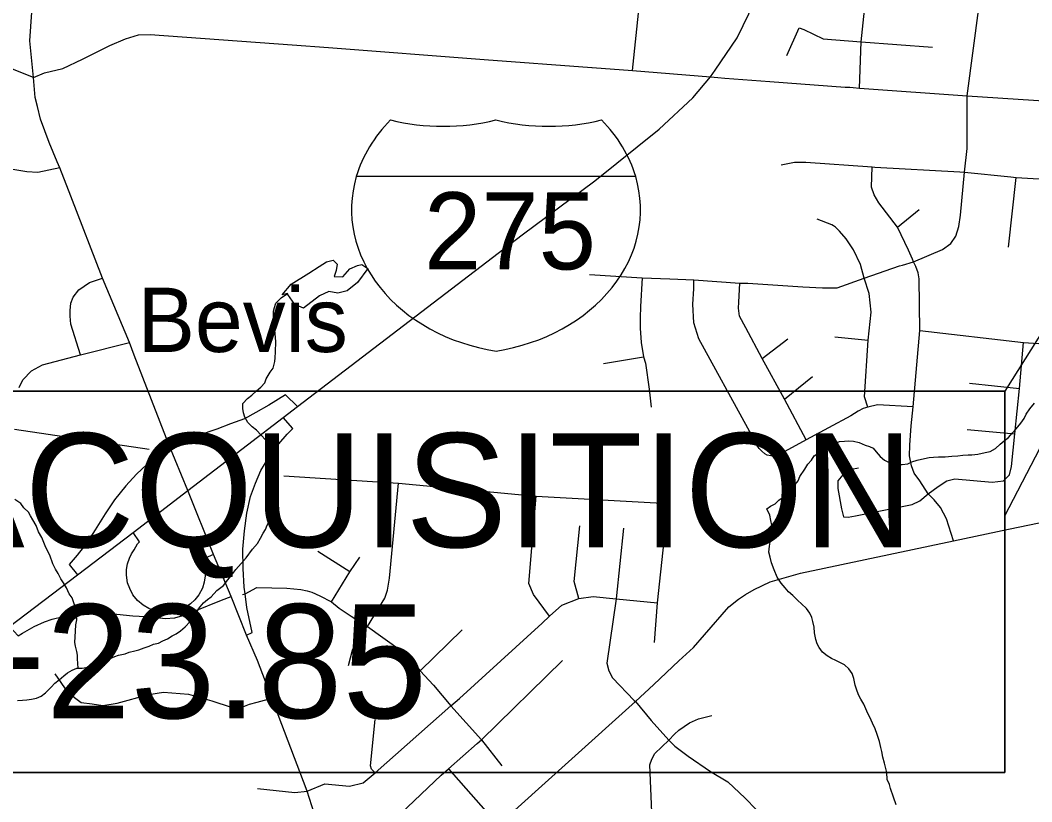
# Model space of a CAD drawing. Extents: x 0 to 34, y 0 to 22.
# Drawn here: x 3.515 to 4.758, y 17.598 to 18.558 of the extents above; entities that cross this region are included whole.
import ezdxf

# ---------------------------------------------------------------- set-up
doc = ezdxf.new("R2010")
doc.units = 0
for name, color, linetype in [('GM_X_County_Road', 7, 'Continuous'), ('GM_X_Interchange_Ramps', 7, 'Continuous'), ('GM_X_Interstate_Location', 7, 'Continuous'), ('GM_X_Interstate_Route', 7, 'Continuous'), ('GM_X_Interstate_Shield', 7, 'Continuous'), ('GM_X_Minor_Lake', 7, 'Continuous'), ('GM_X_Minor_River', 7, 'Continuous'), ('GM_X_Township_Subdivision', 7, 'Continuous'), ('GM_X_Unincorporated_Text', 7, 'Continuous'), ('GM_X_US_Route', 7, 'Continuous'), ('RD_P_Text', 7, 'Continuous'), ('SH_Masking', 7, 'Continuous')]:
    doc.layers.add(name, color=color, linetype=linetype)

msp = doc.modelspace()

# ---------------------------------------------------------------- linework, layer by layer
at = {"layer": 'GM_X_County_Road'}
for points in [[(4.6785, 18.4652), (4.6932, 18.5761), (4.7051, 18.709), (4.7086, 18.7436), (4.7231, 18.9689)], [(4.2674, 18.4962), (4.2756, 18.5744)], [(3.5314, 18.4877), (3.5056, 18.4981), (3.4834, 18.5132), (3.4753, 18.5266), (3.4615, 18.5439), (3.4483, 18.5622)], [(3.5314, 18.4877), (3.5447, 18.4933), (3.5672, 18.4989), (3.5917, 18.5101), (3.6253, 18.5269), (3.6442, 18.5353), (3.6603, 18.5402), (3.6746, 18.5404), (3.8492, 18.5279), (3.8937, 18.5247), (4.085, 18.5097), (4.2173, 18.4999), (4.2176, 18.4999)], [(4.2176, 18.4999), (4.2674, 18.4962), (4.3632, 18.4884), (4.3722, 18.4877), (4.3808, 18.4871)], [(4.3808, 18.4871), (4.4361, 18.483), (4.5287, 18.4761), (4.5341, 18.4757), (4.5384, 18.4754)], [(4.5384, 18.4754), (4.5461, 18.4748), (4.6785, 18.4652), (4.9418, 18.4482), (5.15, 18.4371), (5.2136, 18.4338), (5.4078, 18.4238), (5.4377, 18.4223), (5.5969, 18.4142)], [(3.5889, 18.1471), (3.5773, 18.1847), (3.5762, 18.1946), (3.5765, 18.2018), (3.5773, 18.2108), (3.5799, 18.218), (3.5872, 18.2272), (3.6002, 18.2359), (3.6162, 18.2412)], [(3.5137, 18.1072), (3.5183, 18.1165), (3.529, 18.1275), (3.5423, 18.135), (3.5889, 18.1471), (3.6491, 18.1624)], [(3.5081, 18.0561), (3.6734, 18.0314)], [(3.9249, 17.4139), (4.1024, 17.5697), (4.2708, 17.7213), (4.2935, 17.7424), (4.3241, 17.7714), (4.3423, 17.7879), (4.3557, 17.8032), (4.3855, 17.8377), (4.3976, 17.8473), (4.4059, 17.853), (4.4167, 17.859), (4.4366, 17.8686), (4.4737, 17.8792), (4.6617, 17.9188), (4.7291, 17.933), (4.8264, 17.9531), (4.956, 17.9799), (5.1816, 18.0264), (5.2178, 18.0345), (5.2322, 18.0349), (5.2647, 18.0331), (5.4907, 18.0227), (5.5592, 18.0196)]]:
    msp.add_lwpolyline(points, dxfattribs=at)
at = {"layer": 'GM_X_Interchange_Ramps'}
for points in [[(3.8558, 18.0839), (3.8408, 18.0981), (3.8205, 18.0852), (3.8043, 18.0764), (3.7905, 18.0687), (3.7732, 18.0624), (3.7567, 18.0561), (3.7336, 18.0483), (3.7062, 18.0404), (3.6977, 18.0372)], [(3.7932, 17.8031), (3.8002, 17.8062), (3.7935, 17.8369), (3.7914, 17.8536), (3.7903, 17.8618), (3.7888, 17.8849), (3.7887, 17.9084), (3.7906, 17.931), (3.7933, 17.9528), (3.7981, 17.9733), (3.8041, 17.9898), (3.8108, 18.005), (3.8195, 18.0197), (3.8329, 18.0379), (3.8428, 18.0499), (3.8499, 18.0567), (3.8382, 18.0704)], [(3.6977, 18.0372), (3.6886, 18.0297), (3.682, 18.0233), (3.6705, 18.0125), (3.658, 18.0007), (3.6447, 17.9865), (3.631, 17.9691), (3.6193, 17.9519), (3.6071, 17.9324), (3.5967, 17.9163), (3.5852, 17.9011), (3.5753, 17.8898), (3.5855, 17.8769)], [(3.7523, 17.9019), (3.7421, 17.8975), (3.743, 17.8895), (3.7423, 17.8759), (3.7411, 17.868), (3.7388, 17.8607), (3.7346, 17.8526), (3.7297, 17.8464), (3.7244, 17.8414), (3.7177, 17.8369), (3.7104, 17.8336), (3.7023, 17.8314), (3.6952, 17.8307), (3.6874, 17.8312), (3.68, 17.8328), (3.6729, 17.8356), (3.6659, 17.8397), (3.6591, 17.8456), (3.6535, 17.8526), (3.6495, 17.8601), (3.647, 17.8674), (3.6457, 17.8765), (3.6458, 17.8837), (3.647, 17.8906), (3.6492, 17.8974), (3.6518, 17.9028), (3.6551, 17.9079), (3.6592, 17.9152), (3.6614, 17.9174), (3.6539, 17.9292)], [(3.5019, 17.8134), (3.5125, 17.8021), (3.5177, 17.8053), (3.5323, 17.8134), (3.5449, 17.8194), (3.5543, 17.8225), (3.5679, 17.8259), (3.5818, 17.8276), (3.5997, 17.8288), (3.626, 17.8297), (3.6535, 17.8268), (3.6765, 17.8253), (3.6933, 17.8234), (3.705, 17.8243), (3.7177, 17.8281), (3.7299, 17.8329), (3.7623, 17.8458), (3.7741, 17.8506)]]:
    msp.add_lwpolyline(points, dxfattribs=at)
at = {"layer": 'GM_X_Interstate_Route'}
for points in [[(4.3688, 18.4966), (4.396, 18.5364), (4.4605, 18.6699), (4.5302, 18.8182), (4.5651, 18.8806), (4.6006, 18.9309), (4.6486, 18.9891), (4.7052, 19.0496), (4.7706, 19.1075), (4.9553, 19.2548), (5.2358, 19.4841)], [(3.7943, 18.0368), (3.8382, 18.0704), (3.8558, 18.0839), (4.1317, 18.2944), (4.2208, 18.3608), (4.3, 18.4242), (4.3415, 18.4627), (4.3632, 18.4884), (4.3688, 18.4966)], [(3.721, 17.9807), (3.7943, 18.0368)], [(2.181, 16.4629), (2.2273, 16.5312), (2.2674, 16.589), (2.34, 16.6943), (2.3633, 16.7237), (2.4215, 16.7861), (2.4393, 16.8007), (2.4586, 16.8179), (2.4894, 16.8393), (2.7155, 16.9908), (2.8497, 17.0804), (2.9292, 17.1425), (3.0025, 17.2108), (3.0522, 17.2646), (3.1203, 17.3605), (3.2374, 17.5377), (3.2788, 17.5999), (3.3097, 17.642), (3.3406, 17.6772), (3.3886, 17.7251), (3.5019, 17.8134), (3.5855, 17.8769), (3.6539, 17.9292), (3.721, 17.9807)]]:
    msp.add_lwpolyline(points, dxfattribs=at)
at = {"layer": 'GM_X_Interstate_Shield'}
msp.add_line((4.2713, 18.3661), (3.9279, 18.3661), dxfattribs=at)
msp.add_line((4.2713, 18.3661), (3.9279, 18.3661), dxfattribs=at)
for centre, start_param, end_param in [((4.144, 18.3255), 2.47259, 2.911027), ((4.0347, 18.6054), 4.415841, 5.008937), ((4.1644, 18.6054), 4.415841, 5.008937), ((4.0552, 18.3255), 0.230566, 0.669003), ((4.144, 18.3255), 2.911027, 4.511031), ((4.0552, 18.3255), 4.913747, 6.513751)]:
    msp.add_ellipse(centre, major_axis=(0.2219, 0), ratio=0.8, start_param=start_param, end_param=end_param, dxfattribs=at)
at = {"layer": 'GM_X_Minor_Lake'}
for points in [[(3.8434, 18.2226), (3.837, 18.2207), (3.8479, 18.2338), (3.8695, 18.2475), (3.8822, 18.2556), (3.8914, 18.2615), (3.8994, 18.2636), (3.9046, 18.2585), (3.903, 18.2506), (3.9009, 18.2434), (3.9115, 18.2428), (3.9201, 18.2529), (3.9293, 18.2569), (3.9346, 18.2583), (3.9421, 18.2532), (3.9296, 18.236), (3.9169, 18.2256), (3.9051, 18.2231), (3.8941, 18.2249), (3.8826, 18.2198)], [(3.8826, 18.2198), (3.8629, 18.2046), (3.8523, 18.209), (3.8439, 18.2213), (3.8434, 18.2226)]]:
    msp.add_lwpolyline(points, dxfattribs=at)
at = {"layer": 'GM_X_Minor_River'}
for points in [[(3.8271, 17.9985), (3.8268, 18.0035), (3.827, 18.0092), (3.8282, 18.0149), (3.8283, 18.0206), (3.8273, 18.0255), (3.8255, 18.0313), (3.8215, 18.0375), (3.8163, 18.0429), (3.8111, 18.0487), (3.8055, 18.0549), (3.7999, 18.0588), (3.7947, 18.0642), (3.791, 18.0708), (3.7892, 18.0758), (3.7886, 18.0811), (3.7887, 18.0876), (3.7941, 18.0935), (3.7995, 18.0976), (3.8053, 18.1028), (3.8107, 18.1077), (3.8154, 18.1129), (3.817, 18.1178), (3.8221, 18.1261), (3.8256, 18.1309), (3.8277, 18.1389), (3.8282, 18.1434), (3.8287, 18.1507), (3.8289, 18.1632), (3.8287, 18.1685), (3.8284, 18.1731), (3.8277, 18.1781), (3.8271, 18.1834), (3.8264, 18.188), (3.8262, 18.1941), (3.8263, 18.2009), (3.8275, 18.2054), (3.8292, 18.2107), (3.8357, 18.2171), (3.8434, 18.2226)], [(4.5586, 18.0345), (4.5631, 18.0325), (4.5668, 18.0279), (4.5716, 18.0224), (4.5768, 18.0178), (4.5843, 18.0142), (4.5904, 18.0126), (4.5984, 18.0124), (4.6056, 18.0134), (4.6106, 18.016), (4.6171, 18.0177), (4.6262, 18.0198), (4.6316, 18.0212), (4.6369, 18.0215), (4.6433, 18.0218), (4.6513, 18.022), (4.6597, 18.0226), (4.6669, 18.0232), (4.673, 18.0238), (4.6795, 18.0245), (4.684, 18.0244), (4.6916, 18.0254), (4.7004, 18.0271), (4.7065, 18.0285), (4.7134, 18.0322), (4.7188, 18.0374), (4.7238, 18.0418), (4.7292, 18.0455), (4.7339, 18.0511), (4.7386, 18.0564), (4.7444, 18.0631), (4.7483, 18.0691), (4.7511, 18.0744), (4.7554, 18.0808), (4.7612, 18.0879)], [(4.5914, 17.5945), (4.5878, 17.6041), (4.5842, 17.6148), (4.5832, 17.6194), (4.5803, 17.6259), (4.5797, 17.6343), (4.5783, 17.6393), (4.5769, 17.6458), (4.5747, 17.6531), (4.5734, 17.6603), (4.5723, 17.6649), (4.5706, 17.6725), (4.5677, 17.681), (4.5652, 17.6879), (4.5623, 17.6948), (4.5587, 17.7021), (4.5565, 17.7067), (4.5514, 17.7182), (4.5477, 17.7243), (4.5455, 17.729), (4.5434, 17.7343), (4.5409, 17.7416), (4.5391, 17.7496), (4.537, 17.7557), (4.5329, 17.7615), (4.5277, 17.7666), (4.5228, 17.769), (4.5172, 17.7717), (4.5119, 17.7745), (4.5063, 17.7777), (4.5007, 17.782), (4.4966, 17.7877), (4.4941, 17.7924), (4.4923, 17.7977), (4.4909, 17.8057), (4.4903, 17.8126), (4.4889, 17.8198), (4.4875, 17.8248), (4.4853, 17.8298), (4.4809, 17.8356), (4.4749, 17.8414), (4.4705, 17.8457), (4.4641, 17.8515), (4.4589, 17.8562), (4.4548, 17.8612), (4.45, 17.867), (4.4452, 17.874), (4.4412, 17.8832), (4.438, 17.8916), (4.4362, 17.8989), (4.4348, 17.905), (4.4354, 17.9122), (4.4362, 17.9171), (4.4375, 17.9232), (4.4384, 17.9296), (4.4386, 17.938), (4.4372, 17.9437), (4.4361, 17.9502), (4.4321, 17.9579), (4.4368, 17.9612), (4.4425, 17.9642), (4.4471, 17.9686), (4.4525, 17.9723), (4.4572, 17.9768), (4.4634, 17.9831), (4.4673, 17.988), (4.4708, 17.9925), (4.4728, 17.9978), (4.4791, 18.0068), (4.4826, 18.0128), (4.4872, 18.0177), (4.4904, 18.0233), (4.4988, 18.0285), (4.5042, 18.0325), (4.5104, 18.0366), (4.5158, 18.0384), (4.5215, 18.0406), (4.5276, 18.0412), (4.5329, 18.0415), (4.5386, 18.041), (4.5458, 18.0397), (4.5533, 18.0361), (4.5586, 18.0345)], [(3.5118, 17.7226), (3.5179, 17.7233), (3.5232, 17.7236), (3.5289, 17.7242), (3.535, 17.7256), (3.5407, 17.7281), (3.5461, 17.7322), (3.5531, 17.7393), (3.5574, 17.7442), (3.5628, 17.7482), (3.5686, 17.7531), (3.5732, 17.7568), (3.579, 17.7601), (3.5847, 17.7623), (3.5912, 17.7625), (3.5957, 17.7632), (3.6007, 17.7638), (3.606, 17.7656), (3.6121, 17.7682), (3.6175, 17.7707), (3.6256, 17.7744), (3.6313, 17.7769), (3.6359, 17.7784), (3.6439, 17.7801), (3.6489, 17.7819), (3.6557, 17.7837), (3.6607, 17.7851), (3.6672, 17.7876), (3.6733, 17.7894), (3.6787, 17.7919), (3.6848, 17.7933), (3.6901, 17.7959), (3.6959, 17.7984), (3.7017, 17.8021), (3.7067, 17.8047), (3.712, 17.8084), (3.7175, 17.8132), (3.7237, 17.8196), (3.7275, 17.8241), (3.7314, 17.8293), (3.7342, 17.8353), (3.7404, 17.8428), (3.7451, 17.8469), (3.7497, 17.8499), (3.7567, 17.8577), (3.7648, 17.864), (3.7703, 17.8711), (3.7749, 17.8771), (3.78, 17.8835), (3.7866, 17.891), (3.7928, 17.8981), (3.8006, 17.9086), (3.8065, 17.9157), (3.8104, 17.922), (3.8135, 17.9281), (3.8163, 17.9326), (3.8183, 17.9379), (3.8215, 17.9439), (3.8247, 17.956), (3.826, 17.9621), (3.8269, 17.97), (3.827, 17.975), (3.8265, 17.9856), (3.827, 17.9928), (3.8271, 17.9985)], [(3.5861, 17.7623), (3.5853, 17.7737), (3.5854, 17.7782), (3.5844, 17.7828), (3.583, 17.7893), (3.5823, 17.7939), (3.5824, 17.8011), (3.583, 17.8079), (3.5835, 17.8155), (3.5844, 17.8216), (3.5841, 17.8262), (3.5827, 17.833), (3.5821, 17.8388), (3.5803, 17.8437), (3.5789, 17.8487), (3.5752, 17.8537), (3.5719, 17.861), (3.5682, 17.8672), (3.5649, 17.8722), (3.5616, 17.8787), (3.5583, 17.8841), (3.555, 17.8907), (3.5515, 17.9014), (3.5485, 17.9064), (3.5456, 17.9125), (3.5416, 17.9229), (3.5376, 17.9298), (3.5347, 17.9378), (3.5307, 17.9444), (3.5278, 17.9494), (3.5252, 17.954), (3.5196, 17.9594), (3.5159, 17.9648), (3.5084, 17.9696)]]:
    msp.add_lwpolyline(points, dxfattribs=at)
at = {"layer": 'GM_X_Township_Subdivision'}
for points in [[(4.5461, 18.4748), (4.548, 18.5316), (4.5541, 18.5864), (4.5589, 18.6315)], [(4.4568, 18.5147), (4.4722, 18.5486), (4.4776, 18.5468), (4.5015, 18.5352), (4.548, 18.5316), (4.6359, 18.5252)], [(4.5988, 18.2574), (4.6127, 18.2616), (4.648, 18.2766), (4.6584, 18.284), (4.6645, 18.2929), (4.6683, 18.3047), (4.6704, 18.3186), (4.6751, 18.3717), (4.6785, 18.4006), (4.6785, 18.4652)], [(3.5637, 18.377), (3.5367, 18.371), (3.5232, 18.3719), (3.488, 18.3776), (3.3929, 18.3966), (3.1812, 18.4357)], [(4.4501, 18.3805), (4.4662, 18.3837), (4.4804, 18.384), (4.5617, 18.3779), (4.5648, 18.3777)], [(4.6114, 18.2645), (4.6113, 18.2648), (4.6065, 18.2756), (4.593, 18.304), (4.57, 18.3339), (4.5642, 18.3435), (4.5609, 18.3529), (4.5617, 18.3779)], [(4.5648, 18.3777), (4.6693, 18.372)], [(4.6693, 18.372), (4.6751, 18.3717), (4.7319, 18.3656)], [(4.7294, 18.2794), (4.7387, 18.3649)], [(4.7319, 18.3656), (4.7387, 18.3649), (4.7946, 18.3616)], [(4.593, 18.304), (4.6194, 18.3258)], [(4.5565, 18.0831), (4.5521, 18.0957), (4.557, 18.1651), (4.5603, 18.1995), (4.558, 18.2226), (4.5519, 18.2414), (4.5473, 18.258), (4.5387, 18.2762), (4.5296, 18.2897), (4.5215, 18.2991), (4.5167, 18.3039), (4.5141, 18.3057), (4.5123, 18.307), (4.4943, 18.3136)], [(4.2143, 18.2459), (4.279, 18.2419), (4.313, 18.2406), (4.3427, 18.2391), (4.399, 18.2353), (4.409, 18.2351), (4.4766, 18.2308), (4.5007, 18.2296), (4.5187, 18.2293), (4.5519, 18.2414), (4.5953, 18.2563), (4.5988, 18.2574)], [(4.6154, 18.2555), (4.6153, 18.2557), (4.6127, 18.2616), (4.6114, 18.2645)], [(4.6617, 17.9188), (4.6531, 17.9459), (4.6456, 17.9597), (4.6379, 17.9692), (4.6305, 17.9764), (4.6202, 17.9924), (4.6133, 18.0019), (4.6102, 18.0111), (4.6074, 18.0232), (4.6079, 18.0361), (4.6097, 18.0602), (4.612, 18.0833), (4.6202, 18.1771), (4.6195, 18.2407), (4.6182, 18.2479), (4.6154, 18.2555)], [(4.279, 18.2419), (4.2771, 18.2064), (4.2767, 18.1927), (4.2767, 18.1798), (4.2781, 18.1623), (4.2809, 18.1447), (4.2834, 18.137), (4.2877, 18.105), (4.2901, 18.0829)], [(4.612, 18.0833), (4.5683, 18.0859), (4.5565, 18.0831), (4.5508, 18.0813), (4.5444, 18.0782), (4.5354, 18.0723), (4.4808, 18.0427), (4.4498, 18.0262), (4.4422, 18.023), (4.4372, 18.023), (4.4329, 18.0238), (4.4299, 18.0258), (4.426, 18.0288), (4.4228, 18.0321), (4.4193, 18.0377), (4.4091, 18.0571), (4.3489, 18.1668), (4.3426, 18.1865), (4.3412, 18.2093), (4.3427, 18.2281), (4.3427, 18.2391)], [(4.4808, 18.0427), (4.4539, 18.0928), (4.4267, 18.1429), (4.4064, 18.1805), (4.3986, 18.1948), (4.3975, 18.2046), (4.3979, 18.2119), (4.3985, 18.2198), (4.399, 18.2353)], [(4.5159, 18.1692), (4.557, 18.1651)], [(4.6202, 18.1771), (4.7476, 18.1625), (4.7786, 18.1601)], [(4.4267, 18.1429), (4.458, 18.1669)], [(4.5451, 18.008), (4.5363, 18.0062), (4.5278, 18.0024), (4.5194, 17.9926), (4.5196, 17.9832), (4.524, 17.9579), (4.5263, 17.9484), (4.5322, 17.948), (4.5413, 17.9493), (4.611, 17.9636), (4.6202, 17.968), (4.6305, 17.9764), (4.6426, 17.9854), (4.6533, 17.9926), (4.6634, 17.9949), (4.7093, 17.991), (4.723, 17.9926), (4.7304, 17.9998), (4.733, 18.0101), (4.7369, 18.0502), (4.7428, 18.1059), (4.7476, 18.1625)], [(4.2315, 18.1366), (4.2809, 18.1447)], [(4.4539, 18.0928), (4.4884, 18.1204)], [(4.6815, 18.1126), (4.7428, 18.1059)], [(4.6786, 18.0557), (4.7369, 18.0502)], [(3.8388, 17.9987), (3.9796, 17.9895), (4.1489, 17.9738), (4.3036, 17.965)], [(3.9182, 17.7657), (3.9233, 17.7844), (3.929, 17.7976), (3.9338, 17.8055), (3.9418, 17.8134), (3.9629, 17.8485), (3.9661, 17.8583), (3.9689, 17.8731), (3.9796, 17.9895)], [(4.1652, 17.8262), (4.1458, 17.8527), (4.1397, 17.8665), (4.1489, 17.9738)], [(4.2013, 17.8481), (4.1957, 17.8687), (4.2024, 17.9373)], [(4.2562, 17.9342), (4.2473, 17.8474), (4.2359, 17.7686), (4.2383, 17.7593), (4.2427, 17.7504), (4.2693, 17.7229)], [(4.2944, 17.794), (4.2981, 17.8425), (4.3061, 17.9189)], [(3.9199, 17.8809), (3.8807, 17.9059)], [(3.8975, 17.8437), (3.9199, 17.8809), (3.9321, 17.8986)], [(3.7881, 17.8528), (3.7914, 17.8536), (3.8059, 17.8614), (3.8426, 17.8605), (3.8598, 17.8592), (3.8675, 17.8576), (3.8734, 17.8559), (3.8833, 17.8512), (3.8975, 17.8437), (3.9067, 17.8362), (3.9215, 17.8264), (3.9418, 17.8134), (3.9822, 17.7847), (3.9936, 17.7749), (4.0066, 17.7593), (4.0226, 17.7417), (4.0442, 17.7161), (4.0818, 17.6746), (4.1066, 17.6426)], [(4.1561, 17.8178), (4.1652, 17.8262), (4.1804, 17.8396), (4.2013, 17.8481), (4.219, 17.8503), (4.2473, 17.8474), (4.2981, 17.8425)], [(3.8675, 17.6115), (3.8893, 17.6206), (3.9197, 17.6174), (3.9365, 17.6215), (3.951, 17.634), (4.0442, 17.7161), (4.0549, 17.7251), (4.1561, 17.8178)], [(4.0066, 17.7593), (4.0582, 17.8097)], [(4.0763, 17.6698), (4.0818, 17.6746), (4.1814, 17.7718)], [(3.5575, 17.7553), (3.5731, 17.7328), (3.5901, 17.7203), (3.6036, 17.7187), (3.6165, 17.7166), (3.634, 17.7193), (3.6729, 17.7299), (3.6911, 17.733), (3.7216, 17.7304), (3.7504, 17.7224), (3.774, 17.7145), (3.7846, 17.714), (3.7904, 17.7156), (3.7967, 17.7182), (3.8063, 17.7206), (3.8241, 17.7258)], [(4.2693, 17.7229), (4.2708, 17.7213), (4.2901, 17.6981), (4.3117, 17.6741), (4.3192, 17.6665), (4.3355, 17.6543), (4.363, 17.6356), (4.3842, 17.6228), (4.4055, 17.6026), (4.4193, 17.5888), (4.4209, 17.587)], [(3.951, 17.634), (3.9465, 17.6384), (3.9454, 17.6423), (3.9511, 17.6993)], [(4.319, 17.6813), (4.3243, 17.6865), (4.3374, 17.6955), (4.3484, 17.7003), (4.3646, 17.7043)], [(4.2976, 17.5167), (4.2953, 17.539), (4.2912, 17.5856), (4.2885, 17.6437), (4.2909, 17.6505), (4.2949, 17.6578), (4.3117, 17.6741), (4.319, 17.6813)], [(4.0324, 17.631), (4.0411, 17.6387), (4.0763, 17.6698)], [(4.0411, 17.6387), (4.1024, 17.5697), (4.1239, 17.545), (4.1277, 17.5359), (4.1323, 17.5252), (4.1355, 17.5024), (4.1321, 17.4618), (4.1279, 17.4175), (4.1274, 17.4093), (4.1284, 17.4029), (4.1784, 17.3083), (4.1828, 17.3009), (4.186, 17.2975), (4.191, 17.2954), (4.3329, 17.28), (4.5161, 17.2672), (4.5322, 17.2634), (4.5467, 17.2577), (4.5616, 17.2543), (4.6015, 17.2519), (4.7252, 17.2398), (4.7414, 17.2423), (4.8149, 17.2674)], [(3.9828, 17.584), (4.0324, 17.631), (4.0324, 17.631)], [(3.8067, 17.6146), (3.8525, 17.6097), (3.8675, 17.6115)]]:
    msp.add_lwpolyline(points, dxfattribs=at)
at = {"layer": 'GM_X_US_Route'}
for points in [[(3.5314, 18.4877), (3.5267, 18.5328), (3.5295, 18.568), (3.5372, 18.5994), (3.5945, 18.718), (3.6051, 18.7398)], [(3.5362, 18.452), (3.5335, 18.4631), (3.5314, 18.4877)], [(3.5606, 18.3842), (3.5504, 18.4078), (3.5398, 18.4365), (3.5362, 18.452)], [(3.5771, 18.3422), (3.5637, 18.377), (3.5606, 18.3842)], [(3.6552, 18.1468), (3.6491, 18.1624), (3.6162, 18.2412), (3.5771, 18.3422)], [(3.6977, 18.0372), (3.6552, 18.1468)], [(3.721, 17.9807), (3.6977, 18.0372)], [(3.8849, 17.5574), (3.8675, 17.6115), (3.8241, 17.7258), (3.8067, 17.7717), (3.7932, 17.8031), (3.7741, 17.8506), (3.7523, 17.9019), (3.721, 17.9807)]]:
    msp.add_lwpolyline(points, dxfattribs=at)
at = {"layer": 'RD_P_Text'}
msp.add_lwpolyline([(4.7247, 17.9493), (5.1831, 18.831), (4.7247, 18.1024), (4.7247, 17.9493)], dxfattribs=at)
msp.add_lwpolyline([(2.6967, 18.1024), (4.7247, 18.1024), (4.7247, 17.6342), (2.6967, 17.6342)], close=True, dxfattribs=at)
at = {"layer": 'SH_Masking'}
msp.add_lwpolyline([(4.7247, 18.1024), (2.6967, 18.1024), (2.6967, 17.6342), (4.7247, 17.6342)], close=True, dxfattribs=at)

# ---------------------------------------------------------------- texts
at = {"layer": 'GM_X_Interstate_Location'}
for s in ['-', '.', ',']:
    msp.add_text(s, height=0.000189, dxfattribs=at).set_placement((4.0996, 18.2994))
msp.add_text('275', height=0.000189, rotation=0, dxfattribs=at).set_placement((4.0417, 18.2602))
at = {"layer": 'GM_X_Interstate_Shield'}
msp.add_text('275', height=0.0947, dxfattribs=at).set_placement((4.0111, 18.2521))
at = {"layer": 'GM_X_Unincorporated_Text'}
msp.add_text('Bevis', height=0.07898, rotation=0, dxfattribs=at).set_placement((3.6592, 18.1507))
at = {"layer": 'RD_P_Text'}
for s, p in [('BEGIN ACQUISITION', (2.7609, 17.911)), ('STA. 10+23.85', (2.7609, 17.701))]:
    msp.add_text(s, height=0.14, dxfattribs=at).set_placement(p)

doc.saveas('drawing.dxf')
